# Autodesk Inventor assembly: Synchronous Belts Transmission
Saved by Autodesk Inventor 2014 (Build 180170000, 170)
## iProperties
Created: 2013-12
Part Number: Synchronous Belts Transmission
Document SubType Name: Assembly
Designer: Bram
ClientObjectVersion: 1
Author: Bram
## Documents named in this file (2)
- D:\gDrive\Google Drive\Hobby\3D Printer\3D printer\Inventor\PrinterAssambly\Design Accelerator\Synchronous Belts Transmission2.iam
- D:\gDrive\Google Drive\Hobby\3D Printer\3D printer\Inventor\PrinterAssambly\Design Accelerator\Synchronous Belt2.ipt
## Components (1 placed, 1 different names)
1. Synchronous Belt:1
